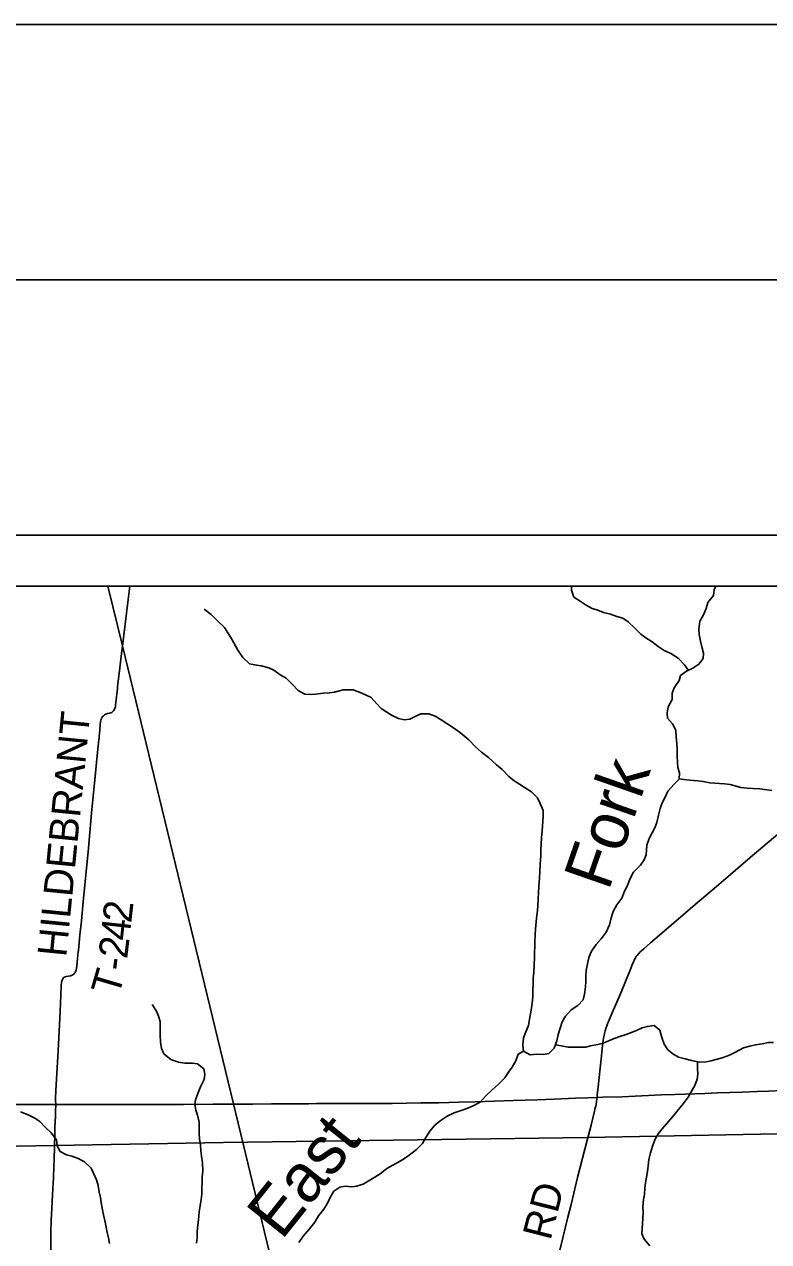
# Model space of a CAD drawing. Extents: x 0 to 48.6, y 0 to 22.
# Drawn here: x 5.632 to 7.09, y 19.616 to 22 of the extents above; entities that cross this region are included whole.
import ezdxf

# ---------------------------------------------------------------- set-up
doc = ezdxf.new("R2010")
doc.units = 0
for name, color, linetype in [('GM_X_Corporation', 7, 'Continuous'), ('GM_X_Major_River', 7, 'Continuous'), ('GM_X_Major_River_Text', 7, 'Continuous'), ('GM_X_Minor_River', 7, 'Continuous'), ('GM_X_Rail_Line', 7, 'Continuous'), ('GM_X_State_Route', 7, 'Continuous'), ('GM_X_Township_Road', 7, 'Continuous'), ('GM_X_Township_Road_Text', 7, 'Continuous'), ('SH_Border', 7, 'Continuous'), ('SH_Cut_Line', 7, 'Continuous'), ('SH_Data', 7, 'Continuous')]:
    doc.layers.add(name, color=color, linetype=linetype)

msp = doc.modelspace()

# ---------------------------------------------------------------- linework, layer by layer
at = {"layer": 'GM_X_Corporation'}
for points in [[(8.9, 20.9), (2.1, 20.9), (2.1, 14.1)], [(5.5264, 17.0064), (5.8387, 17.2541), (6.5365, 17.7727), (6.4996, 17.9212), (6.3396, 18.6531), (6.2759, 18.9159), (6.0412, 19.8859), (5.8236, 20.7829), (5.795, 20.9), (2.1, 20.9), (2.1, 14.1)]]:
    msp.add_lwpolyline(points, dxfattribs=at)
msp.add_lwpolyline([(8.9, 19.5692), (8.9, 20.9), (5.795, 20.9), (5.8236, 20.7829), (6.0412, 19.8859), (6.2759, 18.9159), (6.3396, 18.6531), (6.4996, 17.9212), (6.5365, 17.7727), (6.9471, 18.0777), (7.2261, 18.2847), (8.5348, 19.2897)], close=True, dxfattribs=at)
at = {"layer": 'GM_X_Major_River'}
for points in [[(6.8706, 20.4372), (6.8738, 20.4516), (6.8774, 20.4645), (6.8813, 20.4754), (6.8864, 20.4852), (6.8926, 20.4984), (6.9046, 20.5119), (6.9145, 20.522), (6.9151, 20.5342), (6.9122, 20.5444), (6.9112, 20.5539), (6.9106, 20.568), (6.9104, 20.5805), (6.9098, 20.5915), (6.9088, 20.604), (6.9083, 20.6177), (6.9016, 20.6299), (6.8915, 20.6411), (6.8909, 20.6509), (6.893, 20.6638), (6.9007, 20.6778), (6.9009, 20.6906), (6.9045, 20.7008), (6.9145, 20.7148), (6.9173, 20.7246), (6.9288, 20.7332), (6.9414, 20.7391), (6.9532, 20.7469), (6.9617, 20.7581), (6.9622, 20.7688), (6.9597, 20.7787), (6.9561, 20.792), (6.954, 20.8053), (6.953, 20.8148), (6.9551, 20.8311), (6.9621, 20.8439), (6.9676, 20.8559), (6.9708, 20.868), (6.9816, 20.8816), (6.9832, 20.8925), (6.9861, 20.9)], [(6.1696, 19.6147), (6.1777, 19.6268), (6.1904, 19.6414), (6.2005, 19.6546), (6.2082, 19.667), (6.2186, 19.6797), (6.2256, 19.6914), (6.2314, 19.7042), (6.238, 19.7148), (6.2499, 19.723), (6.2602, 19.7251), (6.273, 19.7234), (6.2825, 19.7248), (6.2955, 19.7288), (6.3184, 19.7422), (6.3287, 19.7493), (6.3421, 19.7593), (6.3536, 19.766), (6.3666, 19.773), (6.3761, 19.779), (6.3857, 19.7853), (6.3999, 19.7965), (6.4114, 19.8085), (6.418, 19.8202), (6.4257, 19.8326), (6.4361, 19.8442), (6.4461, 19.8528), (6.4602, 19.8617), (6.474, 19.8684), (6.4873, 19.8732), (6.4984, 19.8768), (6.5106, 19.8823), (6.5247, 19.8894), (6.5366, 19.9025), (6.5481, 19.9133), (6.56, 19.9242), (6.5727, 19.9373), (6.5804, 19.9478), (6.5874, 19.9576), (6.5944, 19.97), (6.5991, 19.9832), (6.6098, 19.9895), (6.6226, 19.9822), (6.6355, 19.9831), (6.6484, 19.9826), (6.6594, 19.9847), (6.6694, 19.9952), (6.6749, 20.0092), (6.6777, 20.0217), (6.6821, 20.036), (6.6852, 20.0466), (6.6915, 20.0579), (6.7026, 20.0699), (6.716, 20.0788), (6.7264, 20.0897), (6.7288, 20.1011), (6.7309, 20.1151), (6.7314, 20.1257), (6.7319, 20.1367), (6.7325, 20.1473), (6.7349, 20.1605), (6.7374, 20.1727), (6.7428, 20.1851), (6.7517, 20.1983), (6.7614, 20.2091), (6.7714, 20.2223), (6.778, 20.2366), (6.7816, 20.2506), (6.7852, 20.2627), (6.7922, 20.2755), (6.8022, 20.2887), (6.8073, 20.3023), (6.8124, 20.3124), (6.8183, 20.3271), (6.8253, 20.34), (6.8387, 20.3534), (6.8461, 20.3636), (6.8496, 20.3734), (6.8505, 20.3829), (6.851, 20.3927), (6.8557, 20.4059), (6.8619, 20.4165), (6.867, 20.4263), (6.8706, 20.4372)]]:
    msp.add_lwpolyline(points, dxfattribs=at)
at = {"layer": 'GM_X_Minor_River'}
for points in [[(6.9325, 20.7349), (6.9252, 20.7455), (6.9128, 20.7585), (6.8981, 20.7681), (6.8849, 20.7736), (6.8732, 20.7816), (6.8619, 20.7905), (6.8491, 20.7986), (6.8393, 20.8055), (6.8272, 20.8181), (6.8148, 20.83), (6.8043, 20.8369), (6.7921, 20.8405), (6.7797, 20.8451), (6.766, 20.8483), (6.7551, 20.8526), (6.7441, 20.8561), (6.7324, 20.8626), (6.7207, 20.8703), (6.7083, 20.8784), (6.7034, 20.8921), (6.7033, 20.9)], [(6.6098, 19.9895), (6.6081, 20.0007), (6.6098, 20.0151), (6.6141, 20.0268), (6.6191, 20.0393), (6.6215, 20.0518), (6.6247, 20.0692), (6.6267, 20.0832), (6.6276, 20.0954), (6.6281, 20.1087), (6.6286, 20.1212), (6.6287, 20.1322), (6.6295, 20.1439), (6.6304, 20.1576), (6.6309, 20.1724), (6.6314, 20.183), (6.6315, 20.1936), (6.632, 20.2035), (6.6325, 20.2179), (6.6333, 20.2282), (6.635, 20.2494), (6.6367, 20.2646), (6.6375, 20.2748), (6.6384, 20.287), (6.6389, 20.2999), (6.6394, 20.3116), (6.6407, 20.3283), (6.6415, 20.3412), (6.6424, 20.356), (6.6433, 20.3715), (6.6435, 20.3845), (6.6439, 20.3943), (6.6448, 20.4072), (6.6464, 20.4205), (6.6474, 20.4394), (6.6482, 20.4504), (6.6483, 20.4603), (6.6424, 20.4744), (6.6368, 20.4855), (6.6255, 20.497), (6.613, 20.5047), (6.6014, 20.5124), (6.5915, 20.5185), (6.581, 20.527), (6.5675, 20.5408), (6.5565, 20.55), (6.5407, 20.5641), (6.5272, 20.5749), (6.5155, 20.5853), (6.5023, 20.5987), (6.4865, 20.6121), (6.4741, 20.6213), (6.4613, 20.6298), (6.4481, 20.6382), (6.4367, 20.6452), (6.4243, 20.6498), (6.4083, 20.65), (6.3988, 20.6451), (6.3866, 20.6392), (6.3756, 20.6381), (6.3646, 20.6405), (6.3525, 20.6467), (6.3416, 20.6532), (6.331, 20.6602), (6.322, 20.6697), (6.3111, 20.682), (6.3001, 20.687), (6.2896, 20.6917), (6.2759, 20.6967), (6.2562, 20.6969), (6.2395, 20.6921), (6.2292, 20.6911), (6.2178, 20.69), (6.2023, 20.6883), (6.192, 20.6876), (6.1814, 20.6881), (6.1678, 20.6954), (6.1573, 20.7065), (6.1445, 20.7196), (6.1328, 20.7265), (6.1207, 20.735), (6.1109, 20.74), (6.0958, 20.7435), (6.0863, 20.7451), (6.073, 20.7475), (6.0599, 20.7598), (6.0501, 20.7747), (6.0419, 20.7888), (6.0363, 20.7991), (6.03, 20.8087), (6.0236, 20.8186), (6.0093, 20.8324), (5.9976, 20.8442), (5.9841, 20.8546)], [(6.9146, 20.5225), (6.9289, 20.5204), (6.9418, 20.5191), (6.9516, 20.5183), (6.9615, 20.5171), (6.9744, 20.515), (6.9842, 20.5142), (6.9937, 20.5134), (7.0036, 20.5129), (7.0142, 20.5113), (7.0354, 20.5058), (7.0475, 20.5045), (7.0589, 20.5037), (7.0725, 20.5028), (7.0865, 20.5008), (7.0964, 20.4995)], [(5.9691, 19.6133), (5.9704, 19.6239), (5.9705, 19.6353), (5.9717, 19.6493), (5.9726, 19.6588), (5.9742, 19.6743), (5.9762, 19.6864), (5.9782, 19.699), (5.9791, 19.7092), (5.9796, 19.7221), (5.9797, 19.7331), (5.9802, 19.7433), (5.981, 19.7543), (5.9808, 19.7703), (5.9786, 19.7836), (5.9776, 19.7938), (5.9765, 19.8056), (5.9747, 19.817), (5.9741, 19.8277), (5.9742, 19.8383), (5.9743, 19.8501), (5.971, 19.8641), (5.9673, 19.8736), (5.9655, 19.8847), (5.9671, 19.8941), (5.9714, 19.9063), (5.9768, 19.9195), (5.9841, 19.9338), (5.9853, 19.9433), (5.9832, 19.9547), (5.9707, 19.9643), (5.9613, 19.9656), (5.9461, 19.9657), (5.9336, 19.9677), (5.9188, 19.9731), (5.9049, 19.9843), (5.9, 19.9942), (5.8986, 20.0071), (5.898, 20.0212), (5.8974, 20.0348), (5.8979, 20.0473), (5.8942, 20.058), (5.8905, 20.0675), (5.8822, 20.0805)], [(6.672, 20.0019), (6.6874, 19.9988), (6.6973, 19.9972), (6.7212, 19.997), (6.7314, 19.9973), (6.7409, 19.9999), (6.755, 20.002), (6.7653, 20.0049), (6.7778, 20.0101), (6.7873, 20.0139), (6.7984, 20.0179), (6.8087, 20.0213), (6.8193, 20.0249), (6.8311, 20.0294), (6.8422, 20.035), (6.8524, 20.0376), (6.8657, 20.0397), (6.8767, 20.0301), (6.8803, 20.0157), (6.8851, 20.0031), (6.8923, 19.992), (6.902, 19.984), (6.9134, 19.9778), (6.9262, 19.9739), (6.9384, 19.9711), (6.9535, 19.9676), (6.9672, 19.9682), (6.9774, 19.97), (6.9888, 19.9733), (6.9987, 19.9759), (7.0132, 19.9814), (7.0239, 19.9867), (7.0403, 19.9956), (7.0532, 19.9993), (7.0638, 20.0015), (7.0771, 20.0036), (7.0897, 20.0062), (7.0992, 20.0065)], [(6.9507, 19.9682), (6.9507, 19.9554), (6.951, 19.9441), (6.9498, 19.9346), (6.9455, 19.9221), (6.9378, 19.9093), (6.932, 19.8994), (6.9224, 19.8859), (6.9105, 19.8719), (6.9021, 19.8614), (6.8894, 19.8471), (6.881, 19.8369), (6.8733, 19.8271), (6.8675, 19.8169), (6.8621, 19.8033), (6.8582, 19.79), (6.8554, 19.7768), (6.8538, 19.765), (6.8526, 19.7537), (6.8506, 19.7423), (6.8486, 19.7317), (6.8473, 19.7214), (6.8465, 19.7085), (6.8449, 19.6987), (6.8436, 19.6847), (6.8439, 19.6733), (6.8434, 19.6623), (6.8425, 19.6513), (6.8421, 19.641), (6.8412, 19.6315), (6.8461, 19.6209), (6.8573, 19.6079)], [(5.7987, 19.6126), (5.7962, 19.624), (5.7941, 19.6339), (5.7919, 19.6445), (5.7891, 19.6579), (5.7866, 19.6685), (5.7841, 19.6818), (5.7823, 19.6929), (5.7806, 19.7028), (5.778, 19.7131), (5.7759, 19.7264), (5.7727, 19.737), (5.7671, 19.7504), (5.7627, 19.7603), (5.7496, 19.7726), (5.7371, 19.7789), (5.7243, 19.7836), (5.7144, 19.7864), (5.702, 19.7926), (5.6961, 19.8041), (5.6947, 19.8159), (5.6842, 19.8293), (5.6722, 19.8405), (5.6617, 19.8512), (5.652, 19.8578), (5.6388, 19.8648), (5.624, 19.8703)]]:
    msp.add_lwpolyline(points, dxfattribs=at)
at = {"layer": 'GM_X_Rail_Line'}
msp.add_lwpolyline([(2.1, 19.7643), (2.1011, 19.7645), (2.172, 19.7738), (2.2311, 19.7779), (2.3038, 19.7803), (2.4027, 19.7791), (2.7583, 19.782), (3.4579, 19.785), (4.2295, 19.785), (4.6206, 19.7852), (5.0462, 19.7937), (5.6922, 19.8043), (6.0216, 19.8102), (6.7352, 19.82), (7.2096, 19.8291), (8.1004, 19.8459), (8.9, 19.8619)], dxfattribs=at)
at = {"layer": 'GM_X_State_Route'}
for points in [[(6.0414, 19.8854), (6.0792, 19.8856), (6.1158, 19.8858), (6.1314, 19.886), (6.1655, 19.8861), (6.1885, 19.8864), (6.204, 19.8865), (6.2382, 19.8865), (6.3115, 19.8869), (6.3525, 19.887), (6.4085, 19.8878), (6.4439, 19.8882), (6.483, 19.8892), (6.5147, 19.8902), (6.5892, 19.8923), (6.6364, 19.8942), (6.6699, 19.8953), (6.7115, 19.897), (6.7357, 19.8978), (6.7537, 19.8986), (6.7649, 19.899), (6.8028, 19.9001), (6.8798, 19.9035), (6.9058, 19.9043), (6.9648, 19.9064), (6.9897, 19.9075), (7.0139, 19.9082), (7.0381, 19.9089), (7.0673, 19.9102), (7.0896, 19.911), (7.1175, 19.912)], [(5.6016, 19.8845), (5.6585, 19.8846), (5.693, 19.8845), (5.7225, 19.8845), (5.7909, 19.8848), (5.8275, 19.8848), (5.866, 19.8849), (5.8853, 19.8848), (5.9437, 19.8851), (6.0015, 19.8853), (6.0414, 19.8854)]]:
    msp.add_lwpolyline(points, dxfattribs=at)
at = {"layer": 'GM_X_Township_Road'}
for points in [[(5.8239, 20.7824), (5.8291, 20.8252), (5.8349, 20.8739), (5.8381, 20.9)], [(5.8099, 20.6635), (5.8105, 20.6672), (5.8111, 20.6721), (5.814, 20.6994), (5.8144, 20.7028), (5.8189, 20.7401), (5.8214, 20.7629), (5.8239, 20.7824)], [(5.693, 19.8845), (5.6929, 19.8931), (5.6928, 19.8971), (5.6927, 19.9006), (5.6931, 19.9084), (5.6932, 19.9124), (5.6977, 19.9899), (5.702, 20.0668), (5.7033, 20.0985), (5.7039, 20.1165), (5.704, 20.119), (5.7043, 20.1221), (5.7045, 20.1243), (5.705, 20.1264), (5.7056, 20.1282), (5.7062, 20.1295), (5.7069, 20.1309), (5.7083, 20.1327), (5.7099, 20.134), (5.7116, 20.1348), (5.7139, 20.1356), (5.7219, 20.1369), (5.7238, 20.1374), (5.7254, 20.1381), (5.7272, 20.1391), (5.7287, 20.1402), (5.7299, 20.1417), (5.7311, 20.1435), (5.7324, 20.1463), (5.7331, 20.1487), (5.7343, 20.1548), (5.7352, 20.1635), (5.7373, 20.1846), (5.7375, 20.1864), (5.7405, 20.2173), (5.7433, 20.2445), (5.7469, 20.2822), (5.7564, 20.3793), (5.7609, 20.4326), (5.7632, 20.4554), (5.7659, 20.482), (5.7704, 20.5271), (5.7742, 20.5679), (5.7776, 20.5988), (5.7779, 20.6019), (5.7784, 20.6062), (5.7795, 20.618), (5.7803, 20.6292), (5.7811, 20.6348), (5.7816, 20.6371), (5.7822, 20.639), (5.783, 20.6413), (5.7839, 20.6429), (5.7848, 20.6443), (5.7857, 20.6454), (5.7872, 20.6468), (5.7888, 20.6481), (5.7911, 20.6491), (5.7942, 20.6502), (5.7986, 20.651), (5.801, 20.6517), (5.8032, 20.6527), (5.805, 20.6541), (5.8064, 20.6557), (5.8077, 20.6578), (5.8085, 20.6594), (5.8093, 20.6616), (5.8099, 20.6635)], [(6.7537, 19.8986), (6.7541, 19.9029), (6.7559, 19.9196), (6.7617, 19.974), (6.7644, 19.9999), (6.7663, 20.0147), (6.7673, 20.0197), (6.7681, 20.0239), (6.7695, 20.0289), (6.7708, 20.0334), (6.7726, 20.0386), (6.7742, 20.0428), (6.7762, 20.0475), (6.7834, 20.0645), (6.7987, 20.1005), (6.8184, 20.1481), (6.8226, 20.1585), (6.8244, 20.1626), (6.8261, 20.1665), (6.8279, 20.1699), (6.8289, 20.172), (6.8306, 20.1745), (6.8321, 20.1766), (6.8349, 20.1799), (6.8383, 20.1835), (6.8413, 20.1863), (6.8451, 20.1899), (6.8581, 20.2014), (6.9083, 20.2441), (6.9461, 20.2764), (6.9879, 20.3116), (7.0152, 20.3351), (7.0538, 20.3683), (7.1242, 20.4276)], [(5.6833, 19.5752), (5.6837, 19.6336), (5.6843, 19.6584), (5.6852, 19.6813), (5.6869, 19.7086), (5.6884, 19.7412), (5.6895, 19.7631), (5.6902, 19.7775), (5.6914, 19.8265), (5.6916, 19.8408), (5.6924, 19.8613), (5.6928, 19.8718), (5.693, 19.8845)], [(6.6788, 19.5916), (6.6871, 19.626), (6.6963, 19.664), (6.7026, 19.6887), (6.7156, 19.7418), (6.7345, 19.8152), (6.742, 19.844), (6.7489, 19.8717), (6.7495, 19.8748), (6.7502, 19.878), (6.751, 19.8814), (6.7516, 19.8845), (6.752, 19.8868), (6.7524, 19.8891), (6.7528, 19.8917), (6.7532, 19.8943), (6.7537, 19.8986)]]:
    msp.add_lwpolyline(points, dxfattribs=at)
at = {"layer": 'SH_Border'}
msp.add_lwpolyline([(1.5, 21.5), (33.5, 21.5), (33.5, 0.5), (1.5, 0.5)], close=True, dxfattribs=at)
at = {"layer": 'SH_Cut_Line'}
msp.add_lwpolyline([(0, 0), (34, 0), (34, 22), (0, 22)], close=True, dxfattribs=at)
at = {"layer": 'SH_Data'}
for p, q in [((2, 21), (9, 21)), ((2.1, 20.9), (8.9, 20.9))]:
    msp.add_line(p, q, dxfattribs=at)

# ---------------------------------------------------------------- texts
at = {"layer": 'GM_X_Major_River_Text'}
for s, rotation, p in [('Fork', 70.7547, (6.7761, 20.3014)), ('East', 51.3217, (6.1355, 19.6174))]:
    msp.add_text(s, height=0.09469, rotation=rotation, dxfattribs=at).set_placement(p)
at = {"layer": 'GM_X_Township_Road_Text'}
for s, height, rotation, p in [('HILDEBRANT', 0.05682, 84.3943, (5.7137, 20.1724)), ('2', 0.0568, 83.7843, (5.841, 20.2389)), ('4', 0.0568, 83.6615, (5.8371, 20.204)), ('2', 0.0568, 83.1973, (5.8329, 20.1687)), ('-', 0.0568, 82.6719, (5.8299, 20.145)), ('T', 0.0568, 73.6973, (5.816, 20.0948)), ('RD', 0.05682, 75.7263, (6.6623, 19.617))]:
    msp.add_text(s, height=height, rotation=rotation, dxfattribs=at).set_placement(p)

doc.saveas('drawing.dxf')
